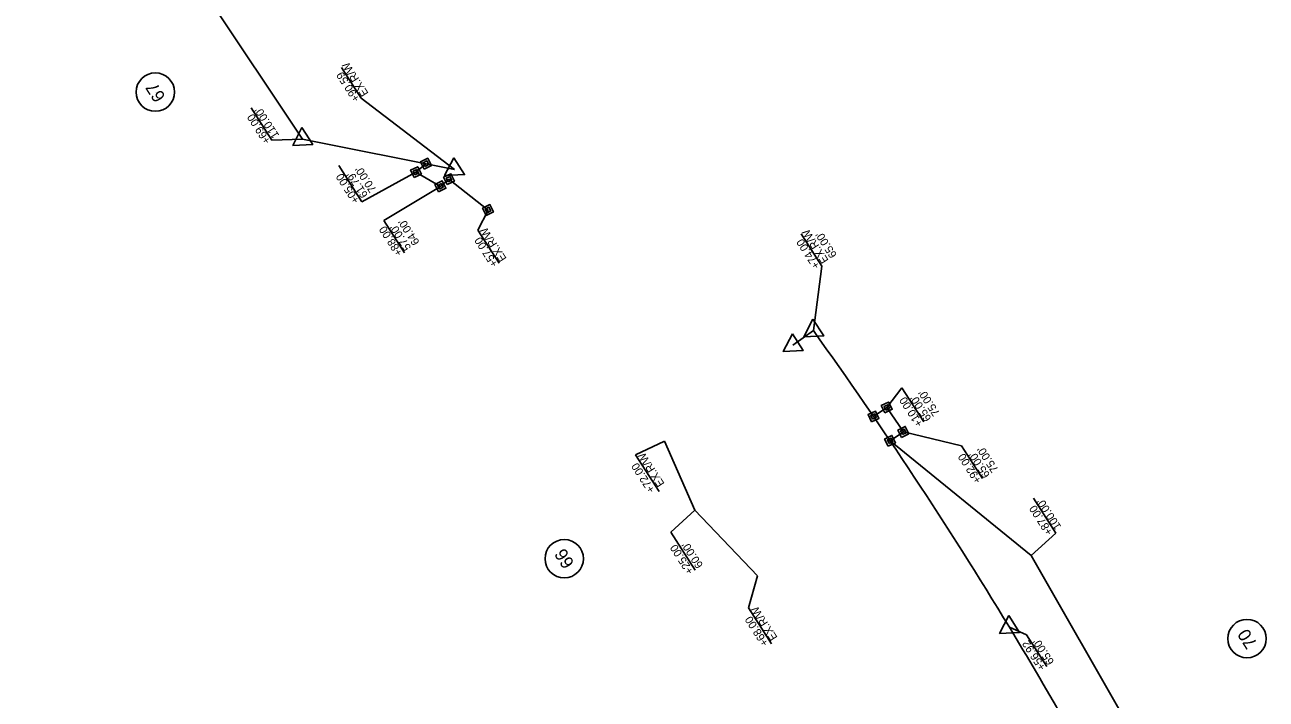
# Model space of a CAD drawing. Extents: x 474184 to 481900, y 489262 to 505659.
# Drawn here: x 477049 to 477825, y 499687 to 500108 of the extents above; entities that cross this region are included whole.
import ezdxf

# ---------------------------------------------------------------- set-up
doc = ezdxf.new("R2010")
doc.units = 0
for name, color, linetype in [('Prop Drainage Structure Outlet Berm Ditch 850 10 Label', 7, 'Continuous'), ('Prop Drainage Structure Pipe CSP 15in', 7, 'Continuous'), ('Prop Drainage Structure Pipe RCP 18in Class IV', 7, 'Continuous'), ('Prop Drainage Structure Pipe RCP 18in Class IV Label', 7, 'Continuous'), ('Prop Drainage Structure Pipe Side Drain 15in Label', 7, 'Continuous'), ('Prop Drainage Structure Pipe Stub Out CELL', 7, 'Continuous'), ('Prop Drainage Structure Plot Symbol 50 Scale', 7, 'Continuous'), ('Prop Earthen Structure Base Ditch Lateral Detail Label', 7, 'Continuous'), ('Prop Earthen Structure False Sump Label', 7, 'Continuous')]:
    doc.layers.add(name, color=color, linetype=linetype)

msp = doc.modelspace()

# ---------------------------------------------------------------- linework, layer by layer
at = {"layer": 'Prop Drainage Structure Outlet Berm Ditch 850 10 Label'}
for p, q in [((477293.64, 500016.17), (477299.92, 500021.49)), ((477308.92, 500007.34), (477293.64, 500016.17)), ((477314.29, 500011.84), (477308.92, 500007.34)), ((477338.66, 499992.53), (477314.29, 500011.84)), ((477579.46, 499863.59), (477587.71, 499869.24)), ((477598.09, 499853.95), (477587.71, 499869.24)), ((477589.8, 499848.36), (477598.09, 499853.95))]:
    msp.add_line(p, q, dxfattribs=at)
at = {"layer": 'Prop Drainage Structure Pipe CSP 15in'}
for p, q in [((477130.89, 500066.2), (477130.89, 500066.2)), ((477386.27, 499774.77), (477386.27, 499774.77)), ((477812.71, 499724.88), (477812.71, 499724.88))]:
    msp.add_line(p, q, dxfattribs=at)
for centre in [(477130.89, 500066.2), (477386.27, 499774.77), (477812.71, 499724.88)]:
    msp.add_circle(centre, 12, dxfattribs=at)
at = {"layer": 'Prop Drainage Structure Pipe RCP 18in Class IV'}
for p, q in [((477222.82, 500036.8), (477222.82, 500036.8)), ((477299.9, 500021.48), (477299.9, 500021.48)), ((477293.64, 500016.17), (477293.64, 500016.17)), ((477317.64, 500017.96), (477317.64, 500017.96)), ((477308.92, 500007.34), (477308.92, 500007.34)), ((477314.29, 500011.84), (477314.29, 500011.84)), ((477338.66, 499992.53), (477338.66, 499992.53)), ((477541.92, 499917.22), (477541.92, 499917.22)), ((477529.11, 499908.04), (477529.11, 499908.04)), ((477587.71, 499869.24), (477587.71, 499869.24)), ((477579.46, 499863.59), (477579.46, 499863.59)), ((477598.09, 499853.95), (477598.09, 499853.95)), ((477589.8, 499848.36), (477589.8, 499848.36)), ((477664.29, 499732.02), (477664.29, 499732.02))]:
    msp.add_line(p, q, dxfattribs=at)
for points in [[(477222.48, 500044.01), (477229.22, 500033.51), (477216.76, 500032.9)], [(477317.3, 500025.16), (477324.04, 500014.66), (477311.58, 500014.05)], [(477541.58, 499924.42), (477548.32, 499913.92), (477535.85, 499913.31)], [(477528.78, 499915.25), (477535.51, 499904.74), (477523.05, 499904.13)], [(477663.95, 499739.22), (477670.69, 499728.72), (477658.22, 499728.11)]]:
    msp.add_lwpolyline(points, close=True, dxfattribs=at)
at = {"layer": 'Prop Drainage Structure Pipe RCP 18in Class IV Label'}
for points in [[(477298.73, 500018.08), (477296.5, 500022.65), (477301.07, 500024.89), (477303.31, 500020.31)], [(477299.32, 500019.78), (477298.2, 500022.07), (477300.49, 500023.18), (477301.6, 500020.9)], [(477292.47, 500012.77), (477290.24, 500017.35), (477294.81, 500019.58), (477297.04, 500015)], [(477293.05, 500014.47), (477291.94, 500016.76), (477294.23, 500017.88), (477295.34, 500015.59)], [(477313.12, 500008.43), (477310.89, 500013.01), (477315.46, 500015.24), (477317.69, 500010.67)], [(477313.7, 500010.14), (477312.59, 500012.42), (477314.88, 500013.54), (477315.99, 500011.25)], [(477307.75, 500003.94), (477305.52, 500008.52), (477310.1, 500010.75), (477312.33, 500006.17)], [(477308.34, 500005.64), (477307.22, 500007.93), (477309.51, 500009.05), (477310.63, 500006.76)], [(477337.49, 499989.13), (477335.26, 499993.7), (477339.83, 499995.93), (477342.07, 499991.36)], [(477338.08, 499990.83), (477336.96, 499993.12), (477339.25, 499994.23), (477340.36, 499991.94)], [(477578.28, 499860.19), (477576.05, 499864.77), (477580.63, 499867), (477582.86, 499862.42)], [(477586.54, 499865.83), (477584.31, 499870.41), (477588.88, 499872.64), (477591.12, 499868.07)], [(477587.13, 499867.54), (477586.01, 499869.82), (477588.3, 499870.94), (477589.41, 499868.65)], [(477578.87, 499861.89), (477577.75, 499864.18), (477580.04, 499865.3), (477581.16, 499863.01)], [(477588.62, 499844.96), (477586.39, 499849.53), (477590.97, 499851.77), (477593.2, 499847.19)], [(477596.91, 499850.55), (477594.68, 499855.12), (477599.26, 499857.36), (477601.49, 499852.78)], [(477597.5, 499852.25), (477596.38, 499854.54), (477598.67, 499855.65), (477599.79, 499853.37)], [(477589.21, 499846.66), (477588.09, 499848.95), (477590.38, 499850.06), (477591.5, 499847.78)]]:
    msp.add_lwpolyline(points, close=True, dxfattribs=at)
at = {"layer": 'Prop Drainage Structure Pipe Side Drain 15in Label'}
for p, q in [((477222.82, 500036.8), (477049.36, 500297.09)), ((477317.64, 500017.96), (477222.82, 500036.8)), ((477541.92, 499917.22), (477529.11, 499908.04))]:
    msp.add_line(p, q, dxfattribs=at)
for centre, radius, start, end in [((475172.81, 498218.83), 2915, 31.27221, 35.63637), ((475792.47, 498595.18), 2190, 27.81302, 31.27221)]:
    msp.add_arc(centre, radius, start, end, dxfattribs=at)
at = {"layer": 'Prop Drainage Structure Pipe Stub Out CELL'}
for p, q in [((477467.94, 499805.17), (477448.98, 499848.18)), ((477677.9, 499776.71), (477589.8, 499848.36)), ((477506.96, 499764.09), (477467.94, 499805.17)), ((477765.25, 499624.13), (477677.9, 499776.71))]:
    msp.add_line(p, q, dxfattribs=at)
at = {"layer": 'Prop Drainage Structure Plot Symbol 50 Scale'}
for p, q in [((477247.12, 500081.63), (477259.46, 500062.4)), ((477259.46, 500062.4), (477317.64, 500017.96)), ((477190.72, 500056.37), (477203.7, 500036.13)), ((477534.25, 499977.75), (477547.24, 499957.51)), ((477547.23, 499957.51), (477541.92, 499917.22)), ((477675.01, 499727.26), (477687.78, 499707.35))]:
    msp.add_line(p, q, dxfattribs=at)
for points in [[(477203.7, 500036.13), (477222.82, 500036.8)], [(477675.01, 499727.26), (477664.29, 499732.02)]]:
    msp.add_lwpolyline(points, dxfattribs=at)
at = {"layer": 'Prop Earthen Structure Base Ditch Lateral Detail Label'}
for p, q in [((477245.39, 500020.33), (477259.9, 499997.71)), ((477293.64, 500016.17), (477259.9, 499997.71)), ((477338.66, 499992.53), (477332.34, 499980)), ((477273.58, 499986.11), (477286.56, 499965.87)), ((477332.34, 499980), (477345.57, 499959.38)), ((477587.71, 499869.24), (477597.21, 499881.56)), ((477610.83, 499860.35), (477597.21, 499881.56)), ((477598.09, 499853.95), (477634.48, 499845.33)), ((477647.54, 499824.96), (477634.48, 499845.33))]:
    msp.add_line(p, q, dxfattribs=at)
msp.add_lwpolyline([(477273.58, 499986.11), (477308.92, 500007.34)], dxfattribs=at)
at = {"layer": 'Prop Earthen Structure False Sump Label'}
for p, q in [((477430.78, 499839.74), (477445.57, 499816.69)), ((477679.35, 499812.65), (477693.43, 499790.69)), ((477452.88, 499791.37), (477467.94, 499805.17)), ((477452.88, 499791.37), (477468.09, 499767.66)), ((477693.43, 499790.69), (477677.9, 499776.71)), ((477501.37, 499744.07), (477515.78, 499721.6))]:
    msp.add_line(p, q, dxfattribs=at)
for points in [[(477430.78, 499839.74), (477448.98, 499848.18)], [(477501.37, 499744.07), (477506.96, 499764.09)]]:
    msp.add_lwpolyline(points, dxfattribs=at)

# ---------------------------------------------------------------- texts
at = {"layer": 'Prop Drainage Structure Pipe CSP 15in'}
for s, p in [('67', (477137.51, 500063.2)), ('66', (477392.85, 499771.91)), ('70', (477819.46, 499721.76))]:
    msp.add_text(s, height=8, rotation=122.68181, dxfattribs=at).set_placement(p)
at = {"layer": 'Prop Drainage Structure Plot Symbol 50 Scale'}
for s, p in [('EX.R/W', (477264.19, 500065.44)), ('+90.59', (477258.93, 500062.07)), ('+69.00', (477203.17, 500035.8)), ("110.00'", (477208.44, 500039.17)), ('EX.R/W', (477551.56, 499961.14)), ("65.00'", (477556.82, 499964.51)), ('+74.00', (477546.3, 499957.76)), ('+56.92', (477687.26, 499707.01)), ("65.00'", (477692.52, 499710.38))]:
    msp.add_text(s, height=5, rotation=122.68181, dxfattribs=at).set_placement(p)
at = {"layer": 'Prop Earthen Structure Base Ditch Lateral Detail Label'}
for s, p in [('+05.00 ', (477258.66, 499998.63)), ("61.79' ", (477263.92, 500002)), ("70.00'", (477269.18, 500005.38)), ('+88.00', (477285.61, 499965.74)), ("57.00'", (477290.87, 499969.11)), ("64.00'", (477296.13, 499972.49)), ('+57.00', (477345.18, 499958.87)), ('EX.R/W', (477350.44, 499962.25)), ('+10.00', (477610.56, 499859.04)), ("65.00'", (477615.82, 499862.42)), ("75.00'", (477621.08, 499865.79)), ("75.00'", (477657.69, 499830.49)), ('+92.00', (477647.17, 499823.74)), ("65.00'", (477652.43, 499827.11))]:
    msp.add_text(s, height=5, rotation=122.68181, dxfattribs=at).set_placement(p)
at = {"layer": 'Prop Earthen Structure False Sump Label'}
for s, p in [('EX.R/W', (477449.1, 499821.61)), ('+72.00', (477443.2, 499817.83)), ('+87.00', (477691.68, 499791.38)), ("100.00'", (477696.94, 499794.75)), ('+25.00', (477467.34, 499766.94)), ("60.00'", (477473.23, 499770.72)), ('EX.R/W', (477519.65, 499725.6)), ('+68.00', (477514.13, 499722.06))]:
    msp.add_text(s, height=5, rotation=122.68181, dxfattribs=at).set_placement(p)

doc.saveas('drawing.dxf')
